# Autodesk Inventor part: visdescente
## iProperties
Shininess: 21.0
Length Units: 11269
Angle Units: 11279
Time Units: 11290
Mass Units: 11283
Length Display Precision: 3
Angle Display Precision: 2
Compacted: True
Created: 2002-01
Part Number: visdescente
Material: Par défaut
Document SubType Name: Modélisation
Designer: pichon
Density: 0.0
Volumn: 0.0
Area: 0.0
PropertySet Name: Model Information
Control State: 0
Master: False
Checked Out: False
Author: pichon
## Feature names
1. Révolution1 [Revolution]
2. Révolution2 [Revolution]
3. Extrusion1
